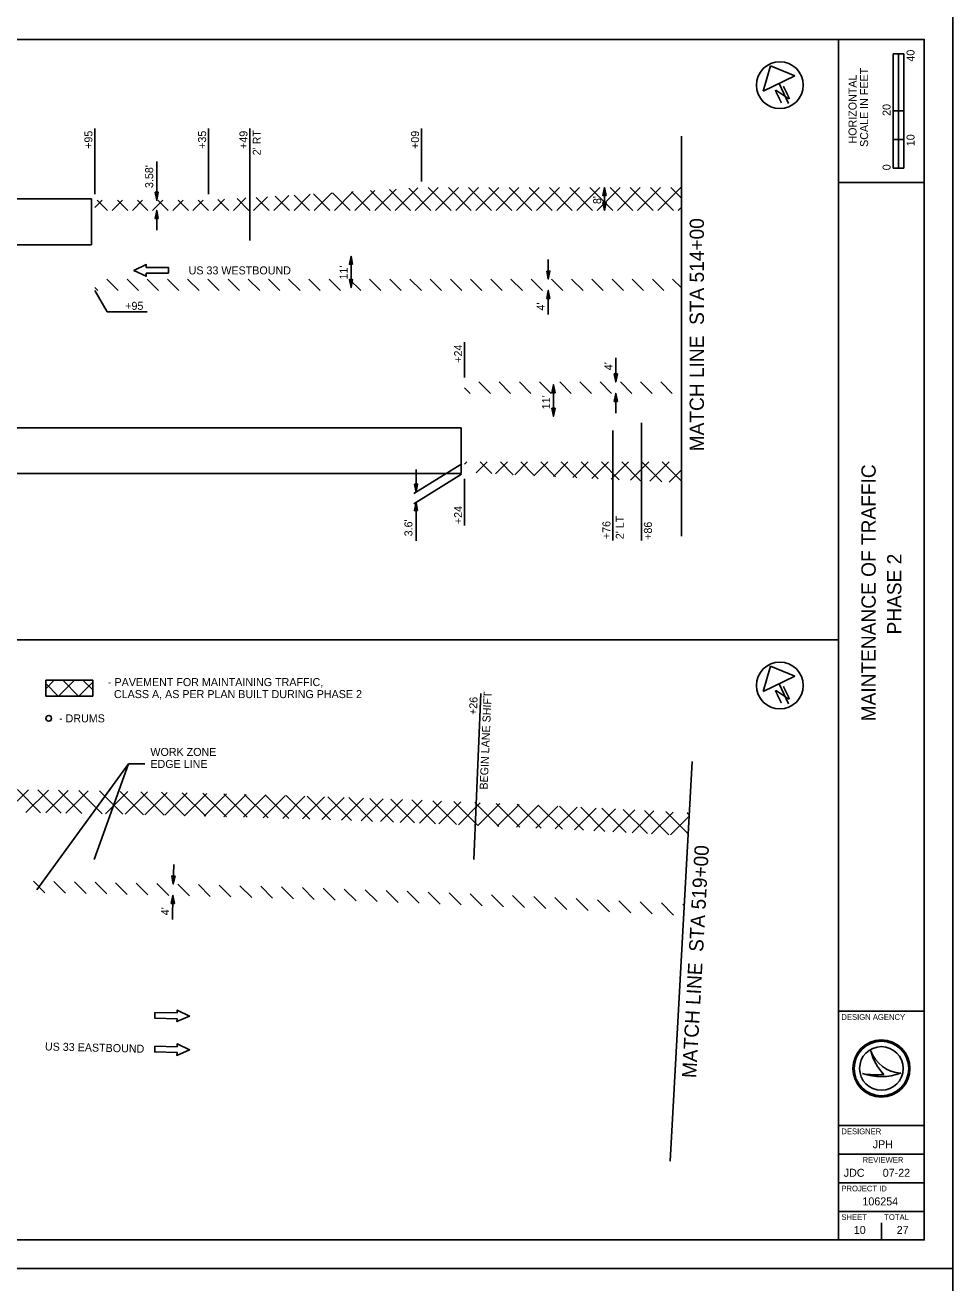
# Model space of a CAD drawing. Extents: x 0 to 5770, y -1320 to 440.
# Drawn here: x 1491.7 to 1816.3, y -445 to -5 of the extents above; entities that cross this region are included whole.
import ezdxf

# ---------------------------------------------------------------- set-up
doc = ezdxf.new("R2010")
doc.units = 0
for name, color, linetype in [('_CIVIL_CONSTRUCTION', 7, 'Continuous'), ('GE_P_Alignment', 7, 'Continuous'), ('GE_P_Alignment_100_Bearings', 7, 'Continuous'), ('GE_P_Alignment_100_Cardinal_Points', 7, 'Continuous'), ('GE_P_Alignment_100_Curve_Data', 7, 'Continuous'), ('GE_P_Alignment_100_Distances', 7, 'Continuous'), ('GE_P_Alignment_100_Stations', 7, 'Continuous'), ('HY_X_Water_Edge', 7, 'Continuous'), ('PM_X_Lane_Line', 7, 'Continuous'), ('PV_X_EOP', 7, 'Continuous')]:
    doc.layers.add(name, color=color, linetype=linetype)

msp = doc.modelspace()

# ---------------------------------------------------------------- linework, layer by layer
at = {"layer": '_CIVIL_CONSTRUCTION'}
for points in [[(1136.32, -440), (1816.32, -440), (1816.32, 0), (1136.32, 0)], [(1136.32, -880), (1816.32, -880), (1816.32, -440), (1136.32, -440)]]:
    msp.add_lwpolyline(points, close=True, dxfattribs=at)
at = {"layer": 'GE_P_Alignment'}
for p, q in [((1776.32, -430), (1776.32, -10)), ((1776.32, -60), (1806.32, -60)), ((1776.32, -350), (1806.32, -350)), ((1776.32, -390), (1806.32, -390)), ((1776.32, -400), (1806.32, -400)), ((1776.32, -410), (1806.32, -410)), ((1776.32, -420), (1806.32, -420))]:
    msp.add_line(p, q, dxfattribs=at)
msp.add_lwpolyline([(1166.32, -10), (1806.32, -10), (1806.32, -430), (1166.32, -430)], close=True, dxfattribs=at)
at = {"layer": 'GE_P_Alignment_100_Bearings'}
for p, q in [((1795.45, -55), (1795.45, -15)), ((1799.2, -15), (1795.45, -15)), ((1795.45, -35), (1795.45, -15)), ((1795.45, -15), (1797.32, -15)), ((1797.32, -15), (1797.33, -15)), ((1797.33, -15), (1797.33, -35)), ((1799.2, -15), (1799.2, -55)), ((1797.33, -35), (1795.45, -35)), ((1799.18, -35), (1797.32, -35)), ((1797.32, -35), (1797.32, -45)), ((1799.18, -45), (1799.18, -35)), ((1797.32, -45), (1795.45, -45)), ((1795.45, -45), (1795.45, -55)), ((1797.32, -55), (1797.32, -45)), ((1797.32, -45), (1799.18, -45)), ((1799.2, -55), (1795.45, -55)), ((1795.45, -55), (1797.32, -55)), ((1787.67, -363.81), (1787.67, -363.81)), ((1784.66, -371.81), (1784.66, -371.81)), ((1791.32, -370), (1791.32, -370)), ((1798.06, -371.63), (1798.06, -371.63)), ((1783.82, -426.5), (1783.82, -426.5)), ((1791.32, -430), (1791.32, -424))]:
    msp.add_line(p, q, dxfattribs=at)
for radius in [10, 9.54, 9.54, 7.64]:
    msp.add_circle((1791.32, -370), radius, dxfattribs=at)
for centre, radius, start, end in [((1798.64, -360.05), 11.6, 198.9257, 198.9319), ((1803.25, -360.6), 15.91, 191.6379, 191.6421), ((1798.64, -360.05), 11.6, 198.9319, 267.1657), ((1803.25, -360.6), 15.91, 191.6421, 226.0947), ((1791.11, -352.6), 20.26, 251.4576, 290.0832), ((1789.28, -346.91), 25.32, 259.4964, 259.4995), ((1791.11, -352.6), 20.26, 251.4527, 251.4576), ((1789.28, -346.91), 25.32, 259.4995, 276.6672)]:
    msp.add_arc(centre, radius, start, end, dxfattribs=at)
at = {"layer": 'GE_P_Alignment_100_Cardinal_Points'}
for p, q in [((1752.53, -19.28), (1749.96, -28.11)), ((1761.04, -22.75), (1752.53, -19.28)), ((1749.96, -28.11), (1761.04, -22.75)), ((1755.5, -25.43), (1758.87, -32.39)), ((1166.32, -220), (1776.32, -220)), ((1752.53, -229.28), (1749.96, -238.11)), ((1749.96, -238.11), (1761.04, -232.75)), ((1761.04, -232.75), (1752.53, -229.28)), ((1755.5, -235.43), (1758.87, -242.39))]:
    msp.add_line(p, q, dxfattribs=at)
for centre in [(1755.78, -26.01), (1755.78, -236.01)]:
    msp.add_circle(centre, 8.2, dxfattribs=at)
at = {"layer": 'GE_P_Alignment_100_Curve_Data'}
for p, q in [((1516.15, -64.11), (1516.15, -41.16)), ((1555.92, -64.11), (1555.92, -41.16)), ((1570.4, -80.34), (1570.4, -41.16)), ((1630.42, -59.72), (1630.42, -41.16)), ((1721.32, -183.82), (1721.32, -43.82)), ((1537.76, -52.71), (1537.76, -66.24)), ((1694.44, -69.82), (1694.44, -61.82)), ((1537.76, -69.82), (1537.76, -76.7)), ((1605.76, -85.82), (1605.76, -96.82)), ((1674.77, -86.94), (1674.77, -93.82)), ((1516.15, -97.82), (1520.41, -105.31)), ((1674.77, -97.82), (1674.77, -106.24)), ((1520.41, -105.31), (1534.38, -105.31)), ((1645.51, -128.26), (1645.51, -115.85)), ((1698.4, -121.4), (1698.4, -129.82)), ((1676.58, -130.82), (1676.58, -141.82)), ((1698.4, -133.82), (1698.4, -140.7)), ((1707.4, -144.07), (1707.4, -185.34)), ((1697.4, -146.8), (1697.4, -185.34)), ((1644.45, -162.12), (1627.73, -172.49)), ((1644.5, -158.45), (1627.77, -168.83)), ((1628.5, -160.44), (1628.5, -168.38)), ((1645.51, -163.72), (1645.51, -180.05)), ((1628.5, -172.02), (1628.5, -185.42)), ((1648.67, -296.94), (1651.13, -238.79)), ((1527.85, -263.47), (1495.79, -307.52)), ((1527.85, -263.47), (1515.93, -296.87)), ((1533.55, -263.47), (1527.85, -263.47)), ((1717.38, -402.4), (1725.09, -262.62)), ((1543.72, -298.59), (1543.56, -305.47)), ((1543.46, -309.47), (1543.26, -317.88))]:
    msp.add_line(p, q, dxfattribs=at)
for points in [[(1541.93, -91.8), (1534.13, -91.8), (1534.13, -92.82), (1529.79, -90.8), (1534.13, -88.77), (1534.13, -89.8), (1541.93, -89.8)], [(1498.93, -234.17), (1515.36, -234.17), (1515.36, -239.7), (1498.93, -239.7)], [(1537.13, -350.4), (1544.92, -350.58), (1544.95, -349.56), (1549.24, -351.69), (1544.85, -353.61), (1544.87, -352.58), (1537.08, -352.4)], [(1537.13, -362.2), (1544.92, -362.39), (1544.95, -361.36), (1549.24, -363.49), (1544.85, -365.41), (1544.87, -364.39), (1537.08, -364.2)]]:
    msp.add_lwpolyline(points, close=True, dxfattribs=at)
at = {"layer": 'GE_P_Alignment_100_Distances'}
for points in [[(1537.2, -63.44), (1538.32, -63.44), (1537.76, -66.24)], [(1695, -64.62), (1693.88, -64.62), (1694.44, -61.82)], [(1538.32, -72.62), (1537.2, -72.62), (1537.76, -69.82)], [(1693.88, -67.02), (1695, -67.02), (1694.44, -69.82)], [(1606.32, -88.62), (1605.2, -88.62), (1605.76, -85.82)], [(1674.21, -91.02), (1675.33, -91.02), (1674.77, -93.82)], [(1605.2, -94.02), (1606.32, -94.02), (1605.76, -96.82)], [(1675.33, -100.62), (1674.21, -100.62), (1674.77, -97.82)], [(1697.84, -127.02), (1698.96, -127.02), (1698.4, -129.82)], [(1677.14, -133.62), (1676.02, -133.62), (1676.58, -130.82)], [(1698.96, -136.62), (1697.84, -136.62), (1698.4, -133.82)], [(1676.02, -139.02), (1677.14, -139.02), (1676.58, -141.82)], [(1627.94, -165.58), (1629.06, -165.58), (1628.5, -168.38)], [(1629.06, -174.82), (1627.94, -174.82), (1628.5, -172.02)], [(1543.07, -302.66), (1544.19, -302.68), (1543.56, -305.47)], [(1543.96, -312.28), (1542.84, -312.25), (1543.46, -309.47)]]:
    msp.add_lwpolyline(points, close=True, dxfattribs=at)
at = {"layer": 'GE_P_Alignment_100_Stations'}
for p, q in [((1561.44, -65.91), (1557.53, -69.82)), ((1568.96, -65.46), (1564.6, -69.82)), ((1565.87, -65.65), (1570.04, -69.82)), ((1576.47, -65.02), (1571.67, -69.82)), ((1572.54, -65.25), (1577.11, -69.82)), ((1583.99, -64.57), (1578.74, -69.82)), ((1579.22, -64.85), (1584.18, -69.82)), ((1591.51, -64.13), (1585.81, -69.82)), ((1585.89, -64.46), (1591.25, -69.82)), ((1592.57, -64.06), (1598.32, -69.82)), ((1599.02, -63.68), (1592.88, -69.82)), ((1599.24, -63.67), (1605.4, -69.82)), ((1606.54, -63.23), (1599.96, -69.82)), ((1605.92, -63.27), (1612.47, -69.82)), ((1614.06, -62.79), (1607.03, -69.82)), ((1612.59, -62.88), (1619.54, -69.82)), ((1621.57, -62.34), (1614.1, -69.82)), ((1619.27, -62.48), (1626.61, -69.82)), ((1629.09, -61.9), (1621.17, -69.82)), ((1625.94, -62.08), (1633.68, -69.82)), ((1636.24, -61.82), (1628.24, -69.82)), ((1632.75, -61.82), (1640.75, -69.82)), ((1643.31, -61.82), (1635.31, -69.82)), ((1639.82, -61.82), (1647.82, -69.82)), ((1650.38, -61.82), (1642.38, -69.82)), ((1646.89, -61.82), (1654.89, -69.82)), ((1657.45, -61.82), (1649.45, -69.82)), ((1653.96, -61.82), (1661.96, -69.82)), ((1664.52, -61.82), (1656.52, -69.82)), ((1661.03, -61.82), (1669.03, -69.82)), ((1671.59, -61.82), (1663.59, -69.82)), ((1668.11, -61.82), (1676.11, -69.82)), ((1678.67, -61.82), (1670.67, -69.82)), ((1675.18, -61.82), (1683.18, -69.82)), ((1685.74, -61.82), (1677.74, -69.82)), ((1682.25, -61.82), (1690.25, -69.82)), ((1692.81, -61.82), (1684.81, -69.82)), ((1689.32, -61.82), (1697.32, -69.82)), ((1699.88, -61.82), (1691.88, -69.82)), ((1696.39, -61.82), (1704.39, -69.82)), ((1706.95, -61.82), (1698.95, -69.82)), ((1703.46, -61.82), (1711.46, -69.82)), ((1714.02, -61.82), (1706.02, -69.82)), ((1710.53, -61.82), (1718.53, -69.82)), ((1721.09, -61.82), (1713.09, -69.82)), ((1717.6, -61.82), (1721.32, -65.53)), ((1518.69, -66.24), (1516.15, -68.78)), ((1516.96, -66.24), (1520.54, -69.82)), ((1525.76, -66.24), (1522.17, -69.82)), ((1524.03, -66.24), (1527.61, -69.82)), ((1532.83, -66.24), (1529.24, -69.82)), ((1531.1, -66.24), (1534.68, -69.82)), ((1539.9, -66.24), (1536.32, -69.82)), ((1538.17, -66.24), (1541.76, -69.82)), ((1546.97, -66.24), (1543.39, -69.82)), ((1545.24, -66.24), (1548.83, -69.82)), ((1554.04, -66.24), (1550.46, -69.82)), ((1552.31, -66.24), (1555.9, -69.82)), ((1559.19, -66.04), (1562.97, -69.82)), ((1721.32, -68.67), (1720.16, -69.82)), ((1516.15, -96.74), (1517.22, -97.82)), ((1520.29, -93.82), (1524.29, -97.82)), ((1527.37, -93.82), (1531.37, -97.82)), ((1534.44, -93.82), (1538.44, -97.82)), ((1541.51, -93.82), (1545.51, -97.82)), ((1548.58, -93.82), (1552.58, -97.82)), ((1555.65, -93.82), (1559.65, -97.82)), ((1562.72, -93.82), (1566.72, -97.82)), ((1569.79, -93.82), (1573.79, -97.82)), ((1576.86, -93.82), (1580.86, -97.82)), ((1583.93, -93.82), (1587.93, -97.82)), ((1591, -93.82), (1595, -97.82)), ((1598.08, -93.82), (1602.08, -97.82)), ((1605.15, -93.82), (1609.15, -97.82)), ((1612.22, -93.82), (1616.22, -97.82)), ((1619.29, -93.82), (1623.29, -97.82)), ((1626.36, -93.82), (1630.36, -97.82)), ((1633.43, -93.82), (1637.43, -97.82)), ((1640.5, -93.82), (1644.5, -97.82)), ((1647.57, -93.82), (1651.57, -97.82)), ((1654.64, -93.82), (1658.64, -97.82)), ((1661.72, -93.82), (1665.72, -97.82)), ((1668.79, -93.82), (1672.79, -97.82)), ((1675.86, -93.82), (1679.86, -97.82)), ((1682.93, -93.82), (1686.93, -97.82)), ((1690, -93.82), (1694, -97.82)), ((1697.07, -93.82), (1701.07, -97.82)), ((1704.14, -93.82), (1708.14, -97.82)), ((1711.21, -93.82), (1715.21, -97.82)), ((1718.28, -93.82), (1721.32, -96.85)), ((1645.51, -131.89), (1647.44, -133.82)), ((1650.51, -129.82), (1654.51, -133.82)), ((1657.58, -129.82), (1661.58, -133.82)), ((1664.65, -129.82), (1668.65, -133.82)), ((1671.72, -129.82), (1675.72, -133.82)), ((1678.79, -129.82), (1682.79, -133.82)), ((1685.86, -129.82), (1689.86, -133.82)), ((1692.93, -129.82), (1696.93, -133.82)), ((1700.01, -129.82), (1704.01, -133.82)), ((1707.08, -129.82), (1711.08, -133.82)), ((1714.15, -129.82), (1718.15, -133.82)), ((1721.22, -129.82), (1721.32, -129.92)), ((1646.31, -157.82), (1645.51, -158.62)), ((1653.38, -157.82), (1649.54, -161.65)), ((1650.97, -157.82), (1655.06, -161.91)), ((1660.45, -157.82), (1656.29, -161.97)), ((1658.04, -157.82), (1662.49, -162.27)), ((1667.52, -157.82), (1663.05, -162.29)), ((1665.11, -157.82), (1669.91, -162.62)), ((1674.59, -157.82), (1669.8, -162.61)), ((1672.18, -157.82), (1677.33, -162.97)), ((1681.66, -157.82), (1676.55, -162.93)), ((1679.25, -157.82), (1684.75, -163.32)), ((1688.73, -157.82), (1683.3, -163.25)), ((1686.32, -157.82), (1692.18, -163.67)), ((1695.8, -157.82), (1690.05, -163.57)), ((1693.4, -157.82), (1699.6, -164.02)), ((1702.87, -157.82), (1696.8, -163.89)), ((1700.47, -157.82), (1707.02, -164.38)), ((1709.95, -157.82), (1703.55, -164.21)), ((1707.54, -157.82), (1714.45, -164.73)), ((1717.02, -157.82), (1710.3, -164.53)), ((1714.61, -157.82), (1721.32, -164.53)), ((1721.32, -160.59), (1717.05, -164.85)), ((1498.93, -237.16), (1501.92, -234.17)), ((1498.93, -235.28), (1503.34, -239.7)), ((1503.46, -239.7), (1508.99, -234.17)), ((1504.88, -234.17), (1510.41, -239.7)), ((1510.53, -239.7), (1515.36, -234.88)), ((1511.95, -234.17), (1515.36, -237.57)), ((1492.91, -272.48), (1485.02, -280.36)), ((1489.01, -272.42), (1497.13, -280.54)), ((1499.87, -272.58), (1491.99, -280.46)), ((1496.19, -272.53), (1504.32, -280.66)), ((1506.82, -272.7), (1498.95, -280.57)), ((1503.37, -272.64), (1511.52, -280.79)), ((1510.57, -272.77), (1518.73, -280.92)), ((1513.77, -272.83), (1505.91, -280.69)), ((1517.78, -272.9), (1525.94, -281.07)), ((1527.63, -273.1), (1519.79, -280.94)), ((1524.99, -273.05), (1533.17, -281.22)), ((1534.55, -273.25), (1526.72, -281.09)), ((1532.22, -273.2), (1540.4, -281.39)), ((1541.47, -273.41), (1533.64, -281.24)), ((1539.45, -273.36), (1547.65, -281.56)), ((1548.37, -273.58), (1540.56, -281.39)), ((1546.69, -273.54), (1554.9, -281.75)), ((1555.27, -273.75), (1547.46, -281.56)), ((1553.95, -273.72), (1562.17, -281.94)), ((1562.16, -273.93), (1554.36, -281.73)), ((1561.21, -273.91), (1569.44, -282.14)), ((1569.04, -274.12), (1561.25, -281.91)), ((1575.91, -274.32), (1568.13, -282.1)), ((1568.48, -274.11), (1576.72, -282.35)), ((1582.78, -274.53), (1575.01, -282.3)), ((1575.76, -274.32), (1584.01, -282.57)), ((1589.63, -274.74), (1581.87, -282.5)), ((1583.05, -274.54), (1591.31, -282.8)), ((1596.48, -274.96), (1588.73, -282.72)), ((1590.35, -274.77), (1598.62, -283.04)), ((1603.32, -275.19), (1595.58, -282.94)), ((1597.66, -275), (1605.94, -283.29)), ((1610.16, -275.43), (1602.42, -283.17)), ((1604.98, -275.25), (1613.27, -283.55)), ((1616.98, -275.68), (1609.26, -283.41)), ((1612.31, -275.51), (1620.61, -283.82)), ((1623.8, -275.93), (1616.08, -283.65)), ((1619.64, -275.78), (1627.96, -284.1)), ((1630.61, -276.19), (1622.9, -283.9)), ((1626.99, -276.05), (1635.32, -284.38)), ((1637.41, -276.46), (1629.71, -284.16)), ((1634.35, -276.34), (1642.69, -284.68)), ((1644.21, -276.74), (1636.51, -284.43)), ((1641.72, -276.63), (1650.07, -284.99)), ((1650.99, -277.02), (1643.31, -284.71)), ((1649.09, -276.94), (1657.46, -285.31)), ((1657.77, -277.31), (1650.1, -284.99)), ((1656.48, -277.26), (1664.86, -285.63)), ((1664.55, -277.61), (1656.88, -285.28)), ((1671.31, -277.92), (1663.65, -285.58)), ((1663.88, -277.58), (1672.27, -285.97)), ((1678.07, -278.23), (1670.41, -285.89)), ((1671.28, -277.92), (1679.69, -286.32)), ((1684.82, -278.56), (1677.17, -286.2)), ((1678.7, -278.26), (1687.11, -286.68)), ((1691.56, -278.89), (1683.92, -286.52)), ((1686.13, -278.62), (1694.55, -287.05)), ((1698.29, -279.22), (1690.66, -286.85)), ((1693.56, -278.99), (1702, -287.42)), ((1705.02, -279.57), (1697.4, -287.19)), ((1701.01, -279.36), (1709.46, -287.81)), ((1711.74, -279.92), (1704.12, -287.53)), ((1708.47, -279.75), (1716.93, -288.21)), ((1718.45, -280.28), (1710.84, -287.88)), ((1715.94, -280.14), (1723.7, -287.9)), ((1723.41, -280.55), (1724.06, -281.2)), ((1724.03, -281.76), (1717.55, -288.24)), ((1494.6, -304.51), (1498.66, -308.57)), ((1501.78, -304.62), (1505.85, -308.69)), ((1508.98, -304.75), (1513.05, -308.82)), ((1516.18, -304.88), (1520.26, -308.96)), ((1523.4, -305.02), (1527.48, -309.11)), ((1530.62, -305.17), (1534.71, -309.27)), ((1537.85, -305.34), (1541.95, -309.43)), ((1545.1, -305.51), (1549.2, -309.61)), ((1552.35, -305.69), (1556.45, -309.8)), ((1559.61, -305.88), (1563.72, -309.99)), ((1566.88, -306.08), (1571, -310.19)), ((1574.16, -306.28), (1578.28, -310.41)), ((1581.45, -306.5), (1585.58, -310.63)), ((1588.75, -306.73), (1592.88, -310.87)), ((1596.05, -306.97), (1600.19, -311.11)), ((1603.37, -307.22), (1607.52, -311.36)), ((1610.7, -307.47), (1614.85, -311.62)), ((1618.04, -307.74), (1622.2, -311.9)), ((1625.38, -308.01), (1629.55, -312.18)), ((1632.74, -308.3), (1636.91, -312.47)), ((1640.11, -308.6), (1644.28, -312.77)), ((1647.48, -308.9), (1651.67, -313.08)), ((1654.87, -309.22), (1659.06, -313.4)), ((1662.27, -309.54), (1666.46, -313.74)), ((1669.67, -309.88), (1673.87, -314.08)), ((1677.09, -310.22), (1681.3, -314.43)), ((1684.52, -310.58), (1688.73, -314.79)), ((1691.95, -310.95), (1696.17, -315.16)), ((1699.4, -311.32), (1703.62, -315.54)), ((1706.86, -311.71), (1711.09, -315.94)), ((1714.33, -312.1), (1718.56, -316.34)), ((1721.8, -312.51), (1722.31, -313.02))]:
    msp.add_line(p, q, dxfattribs=at)
at = {"layer": 'HY_X_Water_Edge'}
for centre in [(1755.78, -26.01), (1755.78, -236.01)]:
    msp.add_circle(centre, 8.2, dxfattribs=at)
at = {"layer": 'PM_X_Lane_Line'}
for p, q in [((1221.32, -65.74), (1514.9, -65.74)), ((1514.9, -81.82), (1514.9, -65.74)), ((1514.9, -81.82), (1221.32, -81.82)), ((1234.76, -145.82), (1644.26, -145.82)), ((1644.26, -161.9), (1644.26, -145.82)), ((1234.76, -161.9), (1644.26, -161.9))]:
    msp.add_line(p, q, dxfattribs=at)
at = {"layer": 'PV_X_EOP'}
msp.add_circle((1499.97, -247.51), 1, dxfattribs=at)

# ---------------------------------------------------------------- texts
at = {"layer": 'GE_P_Alignment_100_Bearings'}
for s, height, rotation, p in [('40', 2.8, 90, (1802.92, -17.75)), ('SCALE IN FEET', 2.8, 90, (1786.67, -47.59)), ('HORIZONTAL', 2.8, 90, (1782.62, -46.42)), ('20', 2.8, 90, (1794.53, -36.75)), ('10', 2.8, 90, (1802.92, -47.35)), ('0', 2.8, 90, (1794.53, -55.77)), ('MATCH LINE  STA 514+00', 5, 90, (1729.23, -154.09)), ('MAINTENANCE OF TRAFFIC', 5, 90, (1789.32, -248.55)), ('PHASE 2', 5, 90, (1798.32, -218.17)), ('MATCH LINE  STA 519+00', 5, 86.8439, (1726.51, -373.46))]:
    msp.add_text(s, height=height, rotation=rotation, dxfattribs=at).set_placement(p)
for s, height, p in [('DESIGN AGENCY', 2, (1777.32, -353)), ('DESIGNER', 2, (1777.32, -393)), ('JPH', 2.8, (1788.28, -397.9)), ('REVIEWER', 2, (1784.75, -403)), ('JDC', 2.8, (1778.14, -407.9)), ('07-22', 2.8, (1791.79, -407.9)), ('PROJECT ID', 2, (1777.32, -413)), ('106254', 2.8, (1784.68, -417.9)), ('SHEET', 2, (1777.32, -423)), ('TOTAL', 2, (1792.32, -423)), ('10', 2.8, (1781.66, -427.9)), ('27', 2.8, (1796.68, -427.9))]:
    msp.add_text(s, height=height, dxfattribs=at).set_placement(p)
at = {"layer": 'GE_P_Alignment_100_Cardinal_Points'}
for p in [(1755.6, -32.57), (1755.6, -242.57)]:
    msp.add_text('N', height=5, rotation=25.8319, dxfattribs=at).set_placement(p)
at = {"layer": 'GE_P_Alignment_100_Curve_Data'}
for s, rotation, p in [('+95', 90, (1515.27, -48.28)), ('+35', 90, (1555.05, -48.28)), ('+49', 90, (1569.52, -48.31)), ("2' RT", 90, (1574.17, -50.54)), ('+09', 90, (1629.55, -48.31)), ("3.58'", 90, (1536.53, -61.99)), ("8'", 90, (1693.26, -67.59)), ("11'", 90, (1604.57, -93.98)), ("4'", 90, (1673.54, -104.82)), ('+24', 90, (1644.63, -123.1)), ("4'", 90, (1697.17, -125.72)), ("11'", 90, (1675.39, -139.37)), ('+24', 90, (1644.63, -179.57)), ("3.6'", 90, (1627.23, -183.84)), ('+76', 90, (1696.52, -184.82)), ("2' LT", 90, (1701.18, -184.84)), ('+86', 90, (1711.02, -185.06)), ('+26', 87.5839, (1649.78, -246.39)), ('BEGIN LANE SHIFT', 87.5839, (1653.52, -272.48)), ("4'", 88.6269, (1542.07, -316.44)), ('US 33 EASTBOUND', 358.6262, (1498.64, -363.68))]:
    msp.add_text(s, height=2.8, rotation=rotation, dxfattribs=at).set_placement(p)
for s, p in [('US 33 WESTBOUND', (1548.93, -92.2)), ('+95', (1526.75, -104.59)), ('- PAVEMENT FOR MAINTAINING TRAFFIC,', (1520.72, -236.23)), ('  CLASS A, AS PER PLAN BUILT DURING PHASE 2', (1520.72, -240.43)), ('- DRUMS', (1503.59, -248.91)), ('WORK ZONE', (1535.56, -260.67)), ('EDGE LINE', (1535.56, -264.87))]:
    msp.add_text(s, height=2.8, dxfattribs=at).set_placement(p)

doc.saveas('drawing.dxf')
